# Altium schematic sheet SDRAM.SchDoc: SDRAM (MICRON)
size A4; Date: 29-OCT-2015; Author: A.B; CompanyName: STMicroelectronics; Organization: MCD/TOOLS/GNB; Address1: 12, Rue Jules HOROWITZ; Address2: 38019 Grenoble; Address3: FRANCE; DocumentNumber: MB1225; Revision: B-01; SheetNumber: 5; SheetTotal: 12; Project: STM32F769I-DISCO
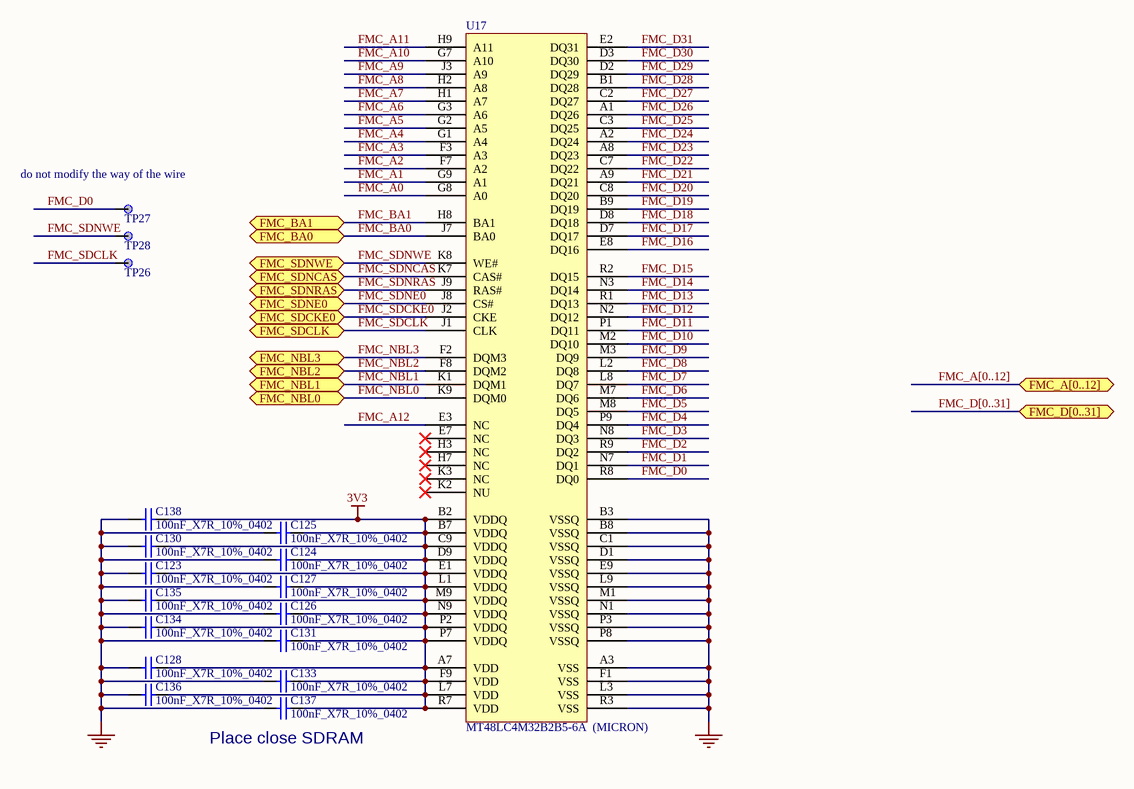
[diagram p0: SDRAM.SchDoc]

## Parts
C123  100nF_X7R_10%_0402  [0402C]
C124  100nF_X7R_10%_0402  [0402C]
C125  100nF_X7R_10%_0402  [0402C]
C126  100nF_X7R_10%_0402  [0402C]
C127  100nF_X7R_10%_0402  [0402C]
C128  100nF_X7R_10%_0402  [0402C]
C130  100nF_X7R_10%_0402  [0402C]
C131  100nF_X7R_10%_0402  [0402C]
C133  100nF_X7R_10%_0402  [0402C]
C134  100nF_X7R_10%_0402  [0402C]
C135  100nF_X7R_10%_0402  [0402C]
C136  100nF_X7R_10%_0402  [0402C]
C137  100nF_X7R_10%_0402  [0402C]
C138  100nF_X7R_10%_0402  [0402C]
TP26  TP  [TP_C40]  (value not drawn)
TP27  TP  [TP_C40]  (value not drawn)
TP28  TP  [TP_C40]  (value not drawn)
U17  MT48LC4M32B2B5-6A  (MICRON)  [FBGA90_0R8_8X13]

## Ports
FMC_A[0..12], FMC_BA0, FMC_BA1, FMC_D[0..31], FMC_NBL0, FMC_NBL1, FMC_NBL2, FMC_NBL3, FMC_SDCKE0, FMC_SDCLK, FMC_SDNCAS, FMC_SDNE0, FMC_SDNRAS, FMC_SDNWE

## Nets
3V3: C123.2 C124.2 C125.2 C126.2 C127.2 C128.2 C130.2 C131.2 C133.2 C134.2 C135.2 C136.2 C137.2 C138.2 U17.A7(VDD) U17.B2(VDDQ) U17.B7(VDDQ) U17.C9(VDDQ) U17.D9(VDDQ) U17.E1(VDDQ) U17.F9(VDD) U17.L1(VDDQ) U17.L7(VDD) U17.M9(VDDQ) U17.N9(VDDQ) U17.P2(VDDQ) U17.P7(VDDQ) U17.R7(VDD)
GND: C123.1 C124.1 C125.1 C126.1 C127.1 C128.1 C130.1 C131.1 C133.1 C134.1 C135.1 C136.1 C137.1 C138.1 U17.A3(VSS) U17.B3(VSSQ) U17.B8(VSSQ) U17.C1(VSSQ) U17.D1(VSSQ) U17.E9(VSSQ) U17.F1(VSS) U17.L3(VSS) U17.L9(VSSQ) U17.M1(VSSQ) U17.N1(VSSQ) U17.P3(VSSQ) U17.P8(VSSQ) U17.R3(VSS)
FMC_A0: U17.G8(A0)
FMC_A1: U17.G9(A1)
FMC_A2: U17.F7(A2)
FMC_A3: U17.F3(A3)
FMC_A4: U17.G1(A4)
FMC_A5: U17.G2(A5)
FMC_A6: U17.G3(A6)
FMC_A7: U17.H1(A7)
FMC_A8: U17.H2(A8)
FMC_A9: U17.J3(A9)
FMC_A10: U17.G7(A10)
FMC_A11: U17.H9(A11)
FMC_A12: U17.E3(NC)
FMC_BA0: U17.J7(BA0) ; port FMC_BA0
FMC_BA1: U17.H8(BA1) ; port FMC_BA1
FMC_D0: TP27.1 U17.R8(DQ0)
FMC_D1: U17.N7(DQ1)
FMC_D2: U17.R9(DQ2)
FMC_D3: U17.N8(DQ3)
FMC_D4: U17.P9(DQ4)
FMC_D5: U17.M8(DQ5)
FMC_D6: U17.M7(DQ6)
FMC_D7: U17.L8(DQ7)
FMC_D8: U17.L2(DQ8)
FMC_D9: U17.M3(DQ9)
FMC_D10: U17.M2(DQ10)
FMC_D11: U17.P1(DQ11)
FMC_D12: U17.N2(DQ12)
FMC_D13: U17.R1(DQ13)
FMC_D14: U17.N3(DQ14)
FMC_D15: U17.R2(DQ15)
FMC_D16: U17.E8(DQ16)
FMC_D17: U17.D7(DQ17)
FMC_D18: U17.D8(DQ18)
FMC_D19: U17.B9(DQ19)
FMC_D20: U17.C8(DQ20)
FMC_D21: U17.A9(DQ21)
FMC_D22: U17.C7(DQ22)
FMC_D23: U17.A8(DQ23)
FMC_D24: U17.A2(DQ24)
FMC_D25: U17.C3(DQ25)
FMC_D26: U17.A1(DQ26)
FMC_D27: U17.C2(DQ27)
FMC_D28: U17.B1(DQ28)
FMC_D29: U17.D2(DQ29)
FMC_D30: U17.D3(DQ30)
FMC_D31: U17.E2(DQ31)
FMC_NBL0: U17.K9(DQM0) ; port FMC_NBL0
FMC_NBL1: U17.K1(DQM1) ; port FMC_NBL1
FMC_NBL2: U17.F8(DQM2) ; port FMC_NBL2
FMC_NBL3: U17.F2(DQM3) ; port FMC_NBL3
FMC_SDCKE0: U17.J2(CKE) ; port FMC_SDCKE0
FMC_SDCLK: TP26.1 U17.J1(CLK) ; port FMC_SDCLK
FMC_SDNCAS: U17.K7(CAS#) ; port FMC_SDNCAS
FMC_SDNE0: U17.J8(CS#) ; port FMC_SDNE0
FMC_SDNRAS: U17.J9(RAS#) ; port FMC_SDNRAS
FMC_SDNWE: TP28.1 U17.K8(WE#) ; port FMC_SDNWE

Not connected (* = marked no-connect by the designer): U17 E7(NC)* H3(NC)* H7(NC)* K2(NU)* K3(NC)*

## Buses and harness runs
bus FMC_A[0..12] = port FMC_A[0..12]
bus FMC_D[0..31] = port FMC_D[0..31]

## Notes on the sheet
- (near TP27) do not modify the way of the wire
- (near C137) Place close SDRAM

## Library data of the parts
C123-C128 C130 C131 C133-C138 = Cap_100nF_X7R_10%_0402: Capacitor,100nF,16V,X7R,10%,0402,YAGEO; Manuf_Part_1: CC0402KRX7R7BB104
TP26-TP28 = TP: Test Point; Description: Test Point CMS
U17 = MT48LC4M32B2B5-6A: SDRAM 128MBIT (4M x 32) 166MHZ 90-VFBGA (8x13); Manuf_Part_1: MT48LC4M32B2B5-6A IT:L TR; Order: MT48LC4M32B2B5-6A IT:L TR-ND; ECCN_US/EU: EAR99/NEC; Provided: ST; Ref St: 9171434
